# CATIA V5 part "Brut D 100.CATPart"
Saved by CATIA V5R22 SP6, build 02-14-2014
Part number: Brut D 76
Bounding box of the stored display mesh (mm): x -38 to 38, y -37.99 to 37.99, z -6.84 to 28.12
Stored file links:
  C:\Users\kremer\Desktop\demo_5x\Brut D 100.CATPart
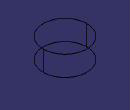
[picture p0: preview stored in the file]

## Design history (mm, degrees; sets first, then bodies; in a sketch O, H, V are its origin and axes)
AxisSystem1: origin (0, 0, 0), X (1, 0, 0), Y (0, 1, 0), Z (0, 0, 1)
Body1 (main body)
  Sketch1 on XY plane of AxisSystem1, origin (0, 0, 0), H (1, 0, 0), V (0, 1, 0)
    circle A1 centre (0, 0) radius 50
    radius A1 = 50
  Pad1: profile Sketch1, direction (0, 0, 1), length 37, opposite side length 9
  Scaling1: ToTransfor Pad1, Reference vertex [YZ plane of AxisSystem1 | ZX plane of AxisSystem1 | XY plane of AxisSystem1], Ratio 0.76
